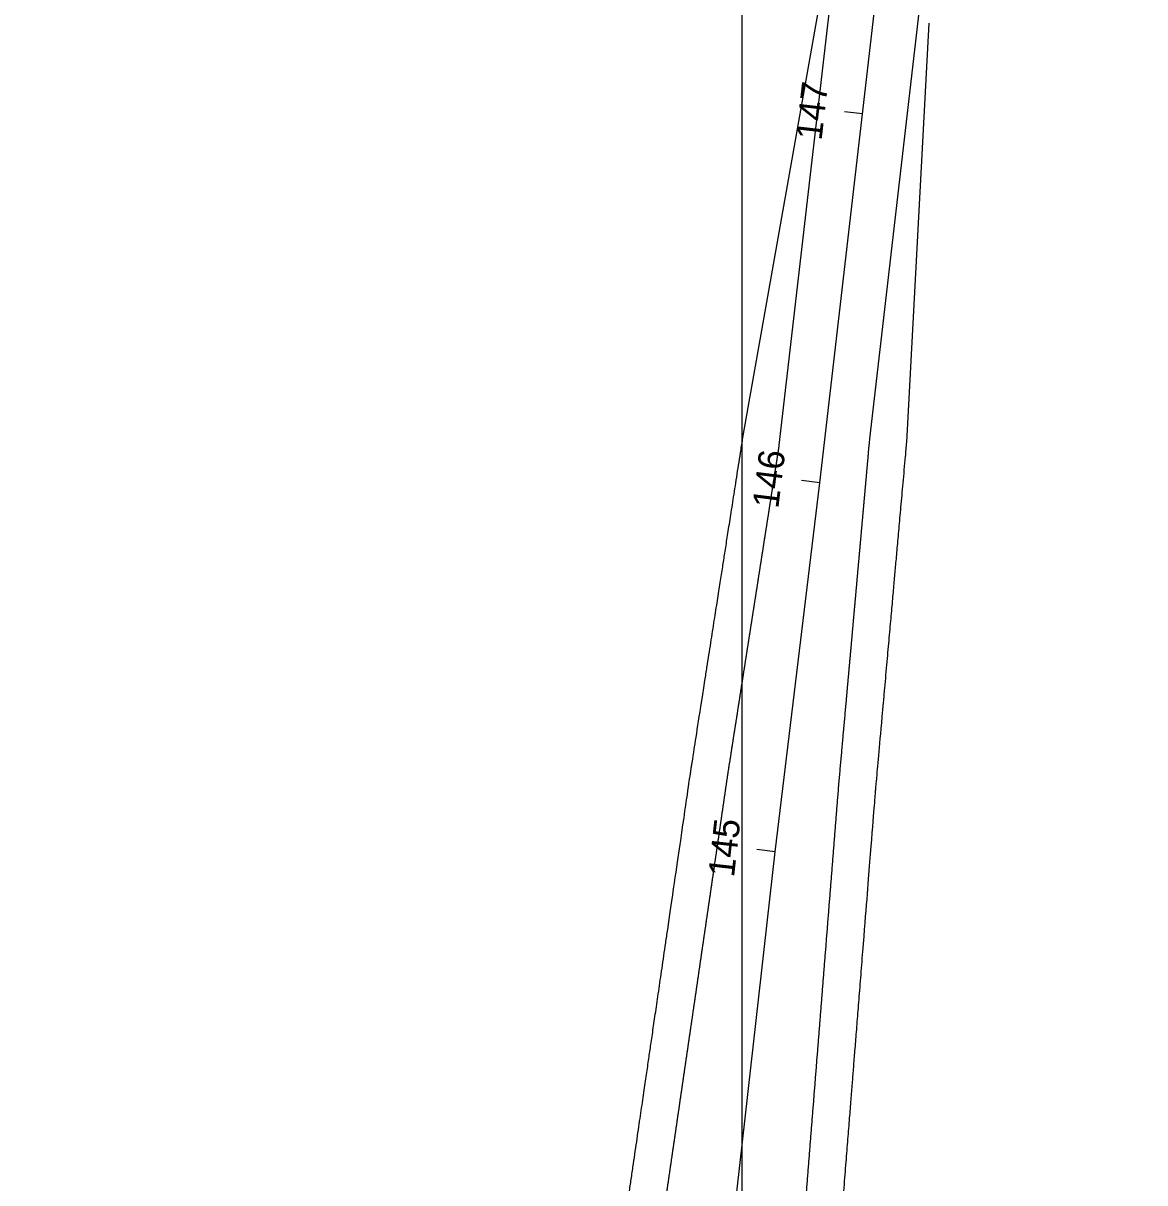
# Model space of a CAD drawing. Extents: x 2318076 to 2324211, y 613525 to 630327.
# Drawn here: x 2320476.3 to 2320778.2, y 628975.4 to 629287.5 of the extents above; entities that cross this region are included whole.
import ezdxf

# ---------------------------------------------------------------- set-up
doc = ezdxf.new("R2010")
doc.units = 0
for name, color, linetype in [('GE_P_CL_50', 7, 'Continuous'), ('PV_P_EOP', 7, 'Continuous'), ('PV_P_Shoulder', 7, 'Continuous'), ('SC_Scratch3', 7, 'Continuous')]:
    doc.layers.add(name, color=color, linetype=linetype)

msp = doc.modelspace()

# ---------------------------------------------------------------- linework, layer by layer
at = {"layer": 'GE_P_CL_50'}
for p, q in [((2320702.26, 629263.11), (2320697.41, 629263.67)), ((2320690.76, 629163.78), (2320685.8, 629164.39)), ((2320678.77, 629064.5), (2320673.8, 629065.06))]:
    msp.add_line(p, q, dxfattribs=at)
msp.add_lwpolyline([(2320476.3, 627307.7), (2320485.22, 627375.57), (2320502.11, 627520.92), (2320519.22, 627676.47), (2320531.82, 627783.89), (2320546.8, 627927.12), (2320554.45, 627991.34), (2320572.51, 628138.41), (2320649.52, 628804.84), (2320678.77, 629064.5), (2320690.76, 629163.78), (2320713.75, 629362.45), (2320725.26, 629461.78), (2320736.97, 629561.09), (2320748.4, 629660.43), (2320759.09, 629759.86), (2320769.62, 629859.3), (2320777.51, 629931.12), (2320778.25, 629937.84)], dxfattribs=at)
at = {"layer": 'PV_P_EOP'}
for points in [[(2320679.85, 629173.88), (2320701.83, 629363.83), (2320708.13, 629418.9), (2320708.13, 629418.9)], [(2320704.21, 629175.59), (2320725.67, 629361.07), (2320731.95, 629415.91), (2320731.95, 629415.91)]]:
    msp.add_lwpolyline(points, dxfattribs=at)
for points in [[(2320669.71, 629109.04), (2320669.76, 629109.34), (2320669.81, 629109.64), (2320669.85, 629109.94), (2320669.9, 629110.24), (2320669.95, 629110.54), (2320670, 629110.84), (2320670.04, 629111.14), (2320670.09, 629111.44), (2320670.14, 629111.74), (2320670.18, 629112.04), (2320670.23, 629112.34), (2320670.28, 629112.64), (2320670.32, 629112.94), (2320670.37, 629113.24), (2320670.42, 629113.54), (2320670.47, 629113.84), (2320670.51, 629114.14), (2320670.56, 629114.44), (2320670.61, 629114.74), (2320670.65, 629115.04), (2320670.7, 629115.35), (2320670.75, 629115.65), (2320670.79, 629115.95), (2320670.84, 629116.25), (2320670.89, 629116.55), (2320670.93, 629116.85), (2320670.98, 629117.15), (2320671.03, 629117.45), (2320671.08, 629117.75), (2320671.12, 629118.05), (2320671.17, 629118.35), (2320671.22, 629118.65), (2320671.26, 629118.95), (2320671.31, 629119.25), (2320671.36, 629119.55), (2320671.4, 629119.85), (2320671.45, 629120.15), (2320671.5, 629120.45), (2320671.55, 629120.75), (2320671.59, 629121.05), (2320671.64, 629121.35), (2320671.69, 629121.65), (2320671.73, 629121.95), (2320671.78, 629122.25), (2320671.83, 629122.55), (2320671.87, 629122.85), (2320671.92, 629123.15), (2320671.97, 629123.45), (2320672.01, 629123.75), (2320672.06, 629124.05), (2320672.11, 629124.35), (2320672.16, 629124.66), (2320672.2, 629124.96), (2320672.25, 629125.26), (2320672.3, 629125.56), (2320672.34, 629125.86), (2320672.39, 629126.16), (2320672.44, 629126.46), (2320672.48, 629126.76), (2320672.53, 629127.06), (2320672.58, 629127.36), (2320672.63, 629127.66), (2320672.67, 629127.96), (2320672.72, 629128.26), (2320672.77, 629128.56), (2320672.81, 629128.86), (2320672.86, 629129.16), (2320672.91, 629129.46), (2320672.95, 629129.76), (2320673, 629130.06), (2320673.05, 629130.36), (2320673.09, 629130.66), (2320673.14, 629130.96), (2320673.19, 629131.26), (2320673.24, 629131.56), (2320673.28, 629131.86), (2320673.33, 629132.16), (2320673.38, 629132.46), (2320673.42, 629132.76), (2320673.47, 629133.06), (2320673.52, 629133.36), (2320673.56, 629133.66), (2320673.61, 629133.97), (2320673.66, 629134.27), (2320673.71, 629134.57), (2320673.75, 629134.87), (2320673.8, 629135.17), (2320673.85, 629135.47), (2320673.89, 629135.77), (2320673.94, 629136.07), (2320673.99, 629136.37), (2320674.03, 629136.67), (2320674.08, 629136.97), (2320674.13, 629137.27), (2320674.17, 629137.57), (2320674.22, 629137.87), (2320674.27, 629138.17), (2320674.32, 629138.47), (2320674.36, 629138.77), (2320674.41, 629139.07), (2320674.46, 629139.37), (2320674.5, 629139.67), (2320674.55, 629139.97), (2320674.6, 629140.27), (2320674.64, 629140.57), (2320674.69, 629140.87), (2320674.74, 629141.17), (2320674.79, 629141.47), (2320674.83, 629141.77), (2320674.88, 629142.07), (2320674.93, 629142.37), (2320674.97, 629142.67), (2320675.02, 629142.97), (2320675.07, 629143.27), (2320675.11, 629143.58), (2320675.16, 629143.88), (2320675.21, 629144.18), (2320675.25, 629144.48), (2320675.3, 629144.78), (2320675.35, 629145.08), (2320675.4, 629145.38), (2320675.44, 629145.68), (2320675.49, 629145.98), (2320675.54, 629146.28), (2320675.58, 629146.58), (2320675.63, 629146.88), (2320675.68, 629147.18), (2320675.72, 629147.48), (2320675.77, 629147.78), (2320675.82, 629148.08), (2320675.87, 629148.38), (2320675.91, 629148.68), (2320675.96, 629148.98), (2320676.01, 629149.28), (2320676.05, 629149.58), (2320676.1, 629149.88), (2320676.15, 629150.18), (2320676.19, 629150.48), (2320676.24, 629150.78), (2320676.29, 629151.08), (2320676.33, 629151.38), (2320676.38, 629151.68), (2320676.43, 629151.98), (2320676.48, 629152.28), (2320676.52, 629152.58), (2320676.57, 629152.89), (2320676.62, 629153.19), (2320676.66, 629153.49), (2320676.71, 629153.79), (2320676.76, 629154.09), (2320676.8, 629154.39), (2320676.85, 629154.69), (2320676.9, 629154.99), (2320676.95, 629155.29), (2320676.99, 629155.59), (2320677.04, 629155.89), (2320677.09, 629156.19), (2320677.13, 629156.49), (2320677.18, 629156.79), (2320677.23, 629157.09), (2320677.27, 629157.39), (2320677.32, 629157.69), (2320677.37, 629157.99), (2320677.41, 629158.29), (2320677.46, 629158.59), (2320677.51, 629158.89), (2320677.56, 629159.19), (2320677.6, 629159.49), (2320677.65, 629159.79), (2320677.7, 629160.09), (2320677.74, 629160.39), (2320677.79, 629160.69), (2320677.84, 629160.99), (2320677.88, 629161.29), (2320677.93, 629161.59), (2320677.98, 629161.89), (2320678.03, 629162.2), (2320678.07, 629162.5), (2320678.12, 629162.8), (2320678.17, 629163.1), (2320678.21, 629163.4), (2320678.26, 629163.7), (2320678.31, 629164), (2320678.35, 629164.3), (2320678.4, 629164.6), (2320678.45, 629164.9), (2320678.49, 629165.2), (2320678.54, 629165.5), (2320678.59, 629165.8), (2320678.64, 629166.1), (2320678.68, 629166.4), (2320678.73, 629166.7), (2320678.78, 629167), (2320678.82, 629167.3), (2320678.87, 629167.6), (2320678.92, 629167.9), (2320678.96, 629168.2), (2320679.01, 629168.5), (2320679.06, 629168.8), (2320679.11, 629169.1), (2320679.15, 629169.4), (2320679.2, 629169.7), (2320679.25, 629170), (2320679.29, 629170.3), (2320679.34, 629170.6), (2320679.39, 629170.9), (2320679.43, 629171.2), (2320679.48, 629171.51), (2320679.53, 629171.81), (2320679.57, 629172.11), (2320679.62, 629172.41), (2320679.67, 629172.71), (2320679.72, 629173.01), (2320679.76, 629173.3), (2320679.81, 629173.59), (2320679.85, 629173.88)], [(2320697.95, 629105.57), (2320697.97, 629105.88), (2320698, 629106.18), (2320698.03, 629106.48), (2320698.05, 629106.78), (2320698.08, 629107.09), (2320698.11, 629107.39), (2320698.14, 629107.69), (2320698.16, 629107.99), (2320698.19, 629108.3), (2320698.22, 629108.6), (2320698.24, 629108.9), (2320698.27, 629109.21), (2320698.3, 629109.51), (2320698.33, 629109.81), (2320698.35, 629110.11), (2320698.38, 629110.42), (2320698.41, 629110.72), (2320698.43, 629111.02), (2320698.46, 629111.32), (2320698.49, 629111.63), (2320698.52, 629111.93), (2320698.54, 629112.23), (2320698.57, 629112.54), (2320698.6, 629112.84), (2320698.62, 629113.14), (2320698.65, 629113.44), (2320698.68, 629113.75), (2320698.7, 629114.05), (2320698.73, 629114.35), (2320698.76, 629114.66), (2320698.79, 629114.96), (2320698.81, 629115.26), (2320698.84, 629115.56), (2320698.87, 629115.87), (2320698.89, 629116.17), (2320698.92, 629116.47), (2320698.95, 629116.77), (2320698.98, 629117.08), (2320699, 629117.38), (2320699.03, 629117.68), (2320699.06, 629117.99), (2320699.08, 629118.29), (2320699.11, 629118.59), (2320699.14, 629118.89), (2320699.17, 629119.2), (2320699.19, 629119.5), (2320699.22, 629119.8), (2320699.25, 629120.1), (2320699.27, 629120.41), (2320699.3, 629120.71), (2320699.33, 629121.01), (2320699.35, 629121.32), (2320699.38, 629121.62), (2320699.41, 629121.92), (2320699.44, 629122.22), (2320699.46, 629122.53), (2320699.49, 629122.83), (2320699.52, 629123.13), (2320699.54, 629123.44), (2320699.57, 629123.74), (2320699.6, 629124.04), (2320699.63, 629124.34), (2320699.65, 629124.65), (2320699.68, 629124.95), (2320699.71, 629125.25), (2320699.73, 629125.55), (2320699.76, 629125.86), (2320699.79, 629126.16), (2320699.82, 629126.46), (2320699.84, 629126.77), (2320699.87, 629127.07), (2320699.9, 629127.37), (2320699.92, 629127.67), (2320699.95, 629127.98), (2320699.98, 629128.28), (2320700.01, 629128.58), (2320700.03, 629128.88), (2320700.06, 629129.19), (2320700.09, 629129.49), (2320700.11, 629129.79), (2320700.14, 629130.1), (2320700.17, 629130.4), (2320700.19, 629130.7), (2320700.22, 629131), (2320700.25, 629131.31), (2320700.28, 629131.61), (2320700.3, 629131.91), (2320700.33, 629132.22), (2320700.36, 629132.52), (2320700.38, 629132.82), (2320700.41, 629133.12), (2320700.44, 629133.43), (2320700.47, 629133.73), (2320700.49, 629134.03), (2320700.52, 629134.33), (2320700.55, 629134.64), (2320700.57, 629134.94), (2320700.6, 629135.24), (2320700.63, 629135.55), (2320700.66, 629135.85), (2320700.68, 629136.15), (2320700.71, 629136.45), (2320700.74, 629136.76), (2320700.76, 629137.06), (2320700.79, 629137.36), (2320700.82, 629137.66), (2320700.84, 629137.97), (2320700.87, 629138.27), (2320700.9, 629138.57), (2320700.93, 629138.88), (2320700.95, 629139.18), (2320700.98, 629139.48), (2320701.01, 629139.78), (2320701.03, 629140.09), (2320701.06, 629140.39), (2320701.09, 629140.69), (2320701.12, 629141), (2320701.14, 629141.3), (2320701.17, 629141.6), (2320701.2, 629141.9), (2320701.22, 629142.21), (2320701.25, 629142.51), (2320701.28, 629142.81), (2320701.31, 629143.11), (2320701.33, 629143.42), (2320701.36, 629143.72), (2320701.39, 629144.02), (2320701.41, 629144.33), (2320701.44, 629144.63), (2320701.47, 629144.93), (2320701.49, 629145.23), (2320701.52, 629145.54), (2320701.55, 629145.84), (2320701.58, 629146.14), (2320701.6, 629146.44), (2320701.63, 629146.75), (2320701.66, 629147.05), (2320701.68, 629147.35), (2320701.71, 629147.66), (2320701.74, 629147.96), (2320701.77, 629148.26), (2320701.79, 629148.56), (2320701.82, 629148.87), (2320701.85, 629149.17), (2320701.87, 629149.47), (2320701.9, 629149.78), (2320701.93, 629150.08), (2320701.96, 629150.38), (2320701.98, 629150.68), (2320702.01, 629150.99), (2320702.04, 629151.29), (2320702.06, 629151.59), (2320702.09, 629151.89), (2320702.12, 629152.2), (2320702.14, 629152.5), (2320702.17, 629152.8), (2320702.2, 629153.11), (2320702.23, 629153.41), (2320702.25, 629153.71), (2320702.28, 629154.01), (2320702.31, 629154.32), (2320702.33, 629154.62), (2320702.36, 629154.92), (2320702.39, 629155.22), (2320702.42, 629155.53), (2320702.44, 629155.83), (2320702.47, 629156.13), (2320702.5, 629156.44), (2320702.52, 629156.74), (2320702.55, 629157.04), (2320702.58, 629157.34), (2320702.61, 629157.65), (2320702.63, 629157.95), (2320702.66, 629158.25), (2320702.69, 629158.56), (2320702.71, 629158.86), (2320702.74, 629159.16), (2320702.77, 629159.46), (2320702.79, 629159.77), (2320702.82, 629160.07), (2320702.85, 629160.37), (2320702.88, 629160.67), (2320702.9, 629160.98), (2320702.93, 629161.28), (2320702.96, 629161.58), (2320702.98, 629161.89), (2320703.01, 629162.19), (2320703.04, 629162.49), (2320703.07, 629162.79), (2320703.09, 629163.1), (2320703.12, 629163.4), (2320703.15, 629163.7), (2320703.17, 629164), (2320703.2, 629164.31), (2320703.23, 629164.61), (2320703.26, 629164.91), (2320703.28, 629165.22), (2320703.31, 629165.52), (2320703.34, 629165.82), (2320703.36, 629166.12), (2320703.39, 629166.43), (2320703.42, 629166.73), (2320703.44, 629167.03), (2320703.47, 629167.34), (2320703.5, 629167.64), (2320703.53, 629167.94), (2320703.55, 629168.24), (2320703.58, 629168.55), (2320703.61, 629168.85), (2320703.63, 629169.15), (2320703.66, 629169.45), (2320703.69, 629169.76), (2320703.72, 629170.06), (2320703.74, 629170.36), (2320703.77, 629170.67), (2320703.8, 629170.97), (2320703.93, 629172.51), (2320704.07, 629174.05), (2320704.21, 629175.59)]]:
    msp.add_open_spline(points, degree=3, dxfattribs=at)
for points in [[(2320659.7, 629042.15), (2320659.83, 629043.06), (2320659.97, 629043.96), (2320660.1, 629044.86), (2320660.23, 629045.76), (2320660.36, 629046.67), (2320660.49, 629047.57), (2320660.63, 629048.47), (2320660.76, 629049.37), (2320660.89, 629050.27), (2320661.02, 629051.18), (2320661.15, 629052.08), (2320661.29, 629052.98), (2320661.42, 629053.88), (2320661.55, 629054.79), (2320661.68, 629055.69), (2320661.81, 629056.59), (2320661.94, 629057.49), (2320662.08, 629058.4), (2320662.21, 629059.3), (2320662.34, 629060.2), (2320662.47, 629061.1), (2320662.6, 629062), (2320662.74, 629062.91), (2320662.87, 629063.81), (2320663, 629064.71), (2320663.13, 629065.61), (2320663.26, 629066.52), (2320663.4, 629067.42), (2320663.53, 629068.32), (2320663.66, 629069.22), (2320663.79, 629070.13), (2320663.92, 629071.03), (2320664.05, 629071.93), (2320664.19, 629072.83), (2320664.32, 629073.73), (2320664.45, 629074.64), (2320664.58, 629075.54), (2320664.71, 629076.44), (2320664.85, 629077.34), (2320664.98, 629078.25), (2320665.11, 629079.15), (2320665.24, 629080.05), (2320665.37, 629080.95), (2320665.5, 629081.86), (2320665.64, 629082.76), (2320665.77, 629083.66), (2320665.9, 629084.56), (2320666.05, 629085.61), (2320666.19, 629086.51), (2320666.33, 629087.42), (2320666.47, 629088.32), (2320666.62, 629089.22), (2320666.76, 629090.12), (2320666.9, 629091.02), (2320667.04, 629091.92), (2320667.18, 629092.82), (2320667.32, 629093.72), (2320667.46, 629094.62), (2320667.6, 629095.52), (2320667.74, 629096.43), (2320667.88, 629097.33), (2320668.02, 629098.23), (2320668.16, 629099.13), (2320668.31, 629100.03), (2320668.45, 629100.93), (2320668.59, 629101.83), (2320668.73, 629102.73), (2320668.87, 629103.63), (2320669.01, 629104.53), (2320669.15, 629105.43), (2320669.29, 629106.34), (2320669.43, 629107.24), (2320669.57, 629108.14), (2320669.71, 629109.04)], [(2320692.39, 629038.47), (2320692.46, 629039.38), (2320692.53, 629040.29), (2320692.6, 629041.2), (2320692.67, 629042.11), (2320692.75, 629043.02), (2320692.82, 629043.93), (2320692.89, 629044.84), (2320692.96, 629045.74), (2320693.03, 629046.65), (2320693.11, 629047.56), (2320693.18, 629048.47), (2320693.25, 629049.38), (2320693.32, 629050.29), (2320693.4, 629051.2), (2320693.47, 629052.11), (2320693.54, 629053.02), (2320693.61, 629053.93), (2320693.68, 629054.83), (2320693.76, 629055.74), (2320693.83, 629056.65), (2320693.9, 629057.56), (2320693.97, 629058.47), (2320694.05, 629059.38), (2320694.12, 629060.29), (2320694.19, 629061.2), (2320694.26, 629062.11), (2320694.33, 629063.02), (2320694.41, 629063.93), (2320694.48, 629064.83), (2320694.55, 629065.74), (2320694.62, 629066.65), (2320694.69, 629067.56), (2320694.77, 629068.47), (2320694.84, 629069.38), (2320694.91, 629070.29), (2320694.98, 629071.2), (2320695.06, 629072.11), (2320695.13, 629073.02), (2320695.2, 629073.92), (2320695.27, 629074.83), (2320695.34, 629075.74), (2320695.42, 629076.65), (2320695.49, 629077.56), (2320695.56, 629078.47), (2320695.63, 629079.38), (2320695.71, 629080.29), (2320695.78, 629081.2), (2320695.83, 629081.96), (2320695.92, 629082.87), (2320696, 629083.77), (2320696.08, 629084.68), (2320696.16, 629085.59), (2320696.24, 629086.5), (2320696.32, 629087.41), (2320696.4, 629088.32), (2320696.48, 629089.22), (2320696.57, 629090.13), (2320696.65, 629091.04), (2320696.73, 629091.95), (2320696.81, 629092.86), (2320696.89, 629093.76), (2320696.97, 629094.67), (2320697.05, 629095.58), (2320697.13, 629096.49), (2320697.22, 629097.4), (2320697.3, 629098.31), (2320697.38, 629099.21), (2320697.46, 629100.12), (2320697.54, 629101.03), (2320697.62, 629101.94), (2320697.7, 629102.85), (2320697.78, 629103.76), (2320697.87, 629104.66), (2320697.95, 629105.57)], [(2320649.95, 628975.38), (2320650.08, 628976.28), (2320650.21, 628977.19), (2320650.34, 628978.09), (2320650.47, 628978.99), (2320650.6, 628979.89), (2320650.74, 628980.8), (2320650.87, 628981.7), (2320651, 628982.6), (2320651.13, 628983.5), (2320651.26, 628984.4), (2320651.4, 628985.31), (2320651.53, 628986.21), (2320651.66, 628987.11), (2320651.79, 628988.01), (2320651.92, 628988.92), (2320652.06, 628989.82), (2320652.19, 628990.72), (2320652.32, 628991.62), (2320652.45, 628992.53), (2320652.58, 628993.43), (2320652.71, 628994.33), (2320652.85, 628995.23), (2320652.98, 628996.13), (2320653.11, 628997.04), (2320653.24, 628997.94), (2320653.37, 628998.84), (2320653.51, 628999.74), (2320653.64, 629000.65), (2320653.77, 629001.55), (2320653.9, 629002.45), (2320654.03, 629003.35), (2320654.16, 629004.26), (2320654.3, 629005.16), (2320654.43, 629006.06), (2320654.56, 629006.96), (2320654.69, 629007.87), (2320654.82, 629008.77), (2320654.96, 629009.67), (2320655.09, 629010.57), (2320655.22, 629011.47), (2320655.35, 629012.38), (2320655.48, 629013.28), (2320655.62, 629014.18), (2320655.75, 629015.08), (2320655.88, 629015.99), (2320656.01, 629016.89), (2320656.14, 629017.79), (2320656.27, 629018.69), (2320656.41, 629019.6), (2320656.54, 629020.5), (2320656.67, 629021.4), (2320656.8, 629022.3), (2320656.93, 629023.2), (2320657.07, 629024.11), (2320657.2, 629025.01), (2320657.33, 629025.91), (2320657.46, 629026.81), (2320657.59, 629027.72), (2320657.73, 629028.62), (2320657.86, 629029.52), (2320657.99, 629030.42), (2320658.12, 629031.33), (2320658.25, 629032.23), (2320658.38, 629033.13), (2320658.52, 629034.03), (2320658.65, 629034.93), (2320658.78, 629035.84), (2320658.91, 629036.74), (2320659.04, 629037.64), (2320659.18, 629038.54), (2320659.31, 629039.45), (2320659.44, 629040.35), (2320659.57, 629041.25), (2320659.7, 629042.15)], [(2320687.04, 628971.2), (2320687.12, 628972.11), (2320687.19, 628973.02), (2320687.26, 628973.93), (2320687.33, 628974.84), (2320687.4, 628975.75), (2320687.48, 628976.66), (2320687.55, 628977.57), (2320687.62, 628978.48), (2320687.69, 628979.38), (2320687.77, 628980.29), (2320687.84, 628981.2), (2320687.91, 628982.11), (2320687.98, 628983.02), (2320688.05, 628983.93), (2320688.13, 628984.84), (2320688.2, 628985.75), (2320688.27, 628986.66), (2320688.34, 628987.57), (2320688.42, 628988.47), (2320688.49, 628989.38), (2320688.56, 628990.29), (2320688.63, 628991.2), (2320688.7, 628992.11), (2320688.78, 628993.02), (2320688.85, 628993.93), (2320688.92, 628994.84), (2320688.99, 628995.75), (2320689.07, 628996.66), (2320689.14, 628997.57), (2320689.21, 628998.47), (2320689.28, 628999.38), (2320689.35, 629000.29), (2320689.43, 629001.2), (2320689.5, 629002.11), (2320689.57, 629003.02), (2320689.64, 629003.93), (2320689.71, 629004.84), (2320689.79, 629005.75), (2320689.86, 629006.66), (2320689.93, 629007.56), (2320690, 629008.47), (2320690.08, 629009.38), (2320690.15, 629010.29), (2320690.22, 629011.2), (2320690.29, 629012.11), (2320690.36, 629013.02), (2320690.44, 629013.93), (2320690.51, 629014.84), (2320690.58, 629015.75), (2320690.65, 629016.65), (2320690.73, 629017.56), (2320690.8, 629018.47), (2320690.87, 629019.38), (2320690.94, 629020.29), (2320691.01, 629021.2), (2320691.09, 629022.11), (2320691.16, 629023.02), (2320691.23, 629023.93), (2320691.3, 629024.84), (2320691.37, 629025.75), (2320691.45, 629026.65), (2320691.52, 629027.56), (2320691.59, 629028.47), (2320691.66, 629029.38), (2320691.74, 629030.29), (2320691.81, 629031.2), (2320691.88, 629032.11), (2320691.95, 629033.02), (2320692.02, 629033.93), (2320692.1, 629034.84), (2320692.17, 629035.74), (2320692.24, 629036.65), (2320692.31, 629037.56), (2320692.39, 629038.47)], [(2320640.19, 628908.61), (2320640.32, 628909.51), (2320640.45, 628910.41), (2320640.58, 628911.32), (2320640.72, 628912.22), (2320640.85, 628913.12), (2320640.98, 628914.02), (2320641.11, 628914.93), (2320641.24, 628915.83), (2320641.37, 628916.73), (2320641.51, 628917.63), (2320641.64, 628918.54), (2320641.77, 628919.44), (2320641.9, 628920.34), (2320642.03, 628921.24), (2320642.17, 628922.14), (2320642.3, 628923.05), (2320642.43, 628923.95), (2320642.56, 628924.85), (2320642.69, 628925.75), (2320642.82, 628926.66), (2320642.96, 628927.56), (2320643.09, 628928.46), (2320643.22, 628929.36), (2320643.35, 628930.27), (2320643.48, 628931.17), (2320643.62, 628932.07), (2320643.75, 628932.97), (2320643.88, 628933.87), (2320644.01, 628934.78), (2320644.14, 628935.68), (2320644.28, 628936.58), (2320644.41, 628937.48), (2320644.54, 628938.39), (2320644.67, 628939.29), (2320644.8, 628940.19), (2320644.93, 628941.09), (2320645.07, 628942), (2320645.2, 628942.9), (2320645.33, 628943.8), (2320645.46, 628944.7), (2320645.59, 628945.6), (2320645.73, 628946.51), (2320645.86, 628947.41), (2320645.99, 628948.31), (2320646.12, 628949.21), (2320646.25, 628950.12), (2320646.39, 628951.02), (2320646.52, 628951.92), (2320646.65, 628952.82), (2320646.78, 628953.73), (2320646.91, 628954.63), (2320647.04, 628955.53), (2320647.18, 628956.43), (2320647.31, 628957.34), (2320647.44, 628958.24), (2320647.57, 628959.14), (2320647.7, 628960.04), (2320647.84, 628960.94), (2320647.97, 628961.85), (2320648.1, 628962.75), (2320648.23, 628963.65), (2320648.36, 628964.55), (2320648.49, 628965.46), (2320648.63, 628966.36), (2320648.76, 628967.26), (2320648.89, 628968.16), (2320649.02, 628969.07), (2320649.15, 628969.97), (2320649.29, 628970.87), (2320649.42, 628971.77), (2320649.55, 628972.67), (2320649.68, 628973.58), (2320649.81, 628974.48), (2320649.95, 628975.38)]]:
    msp.add_spline(points, degree=3, dxfattribs=at)
at = {"layer": 'PV_P_Shoulder'}
for p, q in [((2320669.97, 629175.43), (2320690.38, 629290.93)), ((2320714.17, 629174.7), (2320720.18, 629287.5))]:
    msp.add_line(p, q, dxfattribs=at)
for points, degree in [([(2320659.83, 629110.58), (2320663.21, 629132.2), (2320666.59, 629153.81), (2320669.97, 629175.43)], 2), ([(2320707.91, 629104.68), (2320709.99, 629128.02), (2320712.08, 629151.36), (2320714.17, 629174.7)], 2), ([(2320649.81, 629043.6), (2320651.44, 629054.75), (2320653.48, 629068.69), (2320655.54, 629082.81), (2320655.97, 629085.78), (2320656, 629085.97), (2320656, 629085.99), (2320656, 629086), (2320656.01, 629086.01), (2320656.01, 629086.03), (2320656.01, 629086.07), (2320656.02, 629086.13), (2320656.04, 629086.24), (2320656.05, 629086.32), (2320656.09, 629086.59), (2320656.12, 629086.81), (2320656.16, 629087.09), (2320656.17, 629087.12), (2320656.17, 629087.16), (2320656.17, 629087.16), (2320656.17, 629087.17), (2320656.17, 629087.18), (2320656.18, 629087.2), (2320656.19, 629087.26), (2320656.21, 629087.4), (2320656.34, 629088.22), (2320656.68, 629090.4), (2320657.88, 629098.05), (2320658.96, 629105.01), (2320659.83, 629110.58)], 3), ([(2320702.35, 629037.68), (2320703.24, 629048.87), (2320704.35, 629062.85), (2320705.48, 629077.01), (2320705.72, 629080.02), (2320705.73, 629080.26), (2320705.74, 629080.34), (2320705.74, 629080.38), (2320705.75, 629080.4), (2320705.75, 629080.4), (2320705.75, 629080.41), (2320705.75, 629080.42), (2320705.76, 629080.56), (2320705.77, 629080.69), (2320705.78, 629080.88), (2320705.79, 629080.95), (2320705.79, 629081.02), (2320705.79, 629081.04), (2320705.79, 629081.06), (2320705.79, 629081.06), (2320705.79, 629081.06), (2320705.79, 629081.07), (2320705.79, 629081.07), (2320705.79, 629081.07), (2320705.79, 629081.07), (2320705.8, 629081.08), (2320705.81, 629081.27), (2320705.89, 629082.15), (2320706.09, 629084.42), (2320706.78, 629092.11), (2320707.41, 629099.09), (2320707.91, 629104.68)], 3), ([(2320640.05, 628976.83), (2320643.3, 628999.08), (2320646.56, 629021.34), (2320649.81, 629043.6)], 2), ([(2320697.01, 628970.41), (2320698.79, 628992.83), (2320700.57, 629015.26), (2320702.35, 629037.68)], 2), ([(2320630.29, 628910.06), (2320633.55, 628932.31), (2320636.8, 628954.57), (2320640.05, 628976.83)], 2)]:
    msp.add_open_spline(points, degree=degree, dxfattribs=at)
at = {"layer": 'SC_Scratch3'}
msp.add_line((2320669.87, 614778.41), (2320669.87, 630327.22), dxfattribs=at)

# ---------------------------------------------------------------- texts
at = {"layer": 'GE_P_CL_50'}
for s, rotation, p in [('147', 83.4799, (2320691.22, 629255.78)), ('146', 83.0008, (2320679.56, 629156.69)), ('145', 83.5732, (2320667.65, 629057.44))]:
    msp.add_text(s, height=7, rotation=rotation, dxfattribs=at).set_placement(p)

doc.saveas('drawing.dxf')
